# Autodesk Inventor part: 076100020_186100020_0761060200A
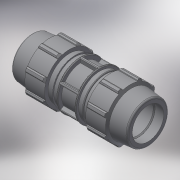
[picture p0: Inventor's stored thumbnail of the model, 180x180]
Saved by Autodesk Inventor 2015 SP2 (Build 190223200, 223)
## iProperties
Created: 2017-02
Part Number: 076100020_186100020_0761060200A
Material: Generic
Description: PLASSON REPAIR COUPLER 20
Document SubType Name: Modeling
Designer: KIM
Mass: 111.998 g
Surface Area: 295.118 cm^2
Volume: 111.998 cm^3
Density: 1 g/cm^3
Appearance: Default
Author: KIM
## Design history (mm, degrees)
derived "07610.ipt"
feature "Solid1::07610.ipt"
tag "TaggingFeature1"
body "Solid1"
other parameters: "d1" = 122, "d4" = 10.16667, "d5" = 17.42857, "d7" = 48, "d8" = 36, "d9" = 17.42857, "d11" = 3.48571, "d12" = 38.4, "d13" = 120 deg, "d15" = 12 deg, "d16" = 43.2, "d18" = 1, "d19" = 35 deg, "d20" = 17.5 deg, "d21" = 44.64, "d23" = 0, "d25" = 360 deg, "d27" = 0.96, "d33" = 0.4, "d34" = 2.4, "d36" = 0, "d37" = 0.4, "d38" = 0.4, "d40" = 360 deg, "d42" = 21.96, "d43" = 1.44, "d46" = 0.6, "d50" = 3.83429, "d51" = 38.4, "E_" = 48, "H_" = 122, "l_" = 78, "d49" = 11.15429
